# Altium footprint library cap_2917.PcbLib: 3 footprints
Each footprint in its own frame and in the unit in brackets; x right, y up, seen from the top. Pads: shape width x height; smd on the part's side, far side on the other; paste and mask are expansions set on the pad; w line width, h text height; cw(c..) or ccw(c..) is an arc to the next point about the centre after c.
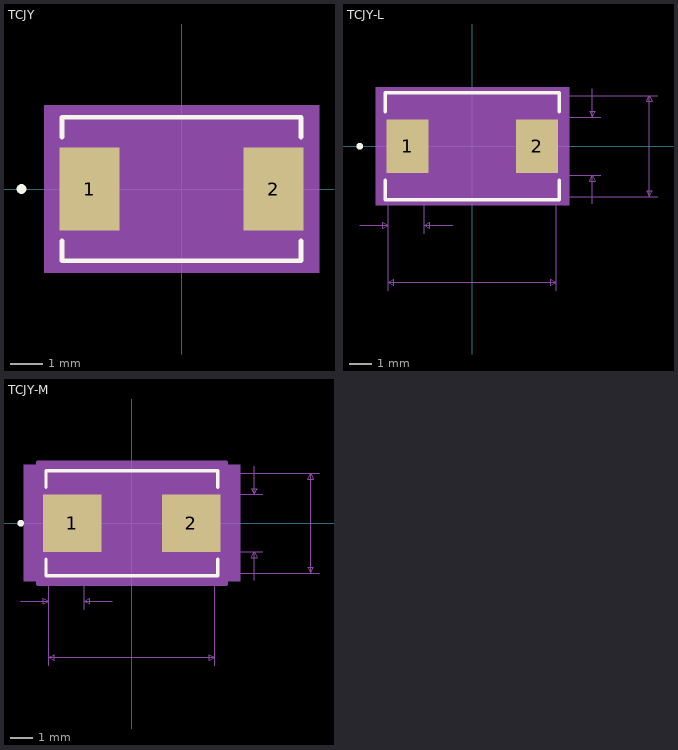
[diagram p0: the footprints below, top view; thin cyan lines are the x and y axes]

## TCJY [mil]
pads (2):
  rect 74x102 smd: 1(-113.5,0) 2(113.5,0)
Top Overlay:
  circle w6: c-197.5,0 r3
  lines w6: -147.5,-64.1 -147.5,-88.5 147.5,-88.5 147.5,-64.1 ; -147.5,64.1 -147.5,88.5 147.5,88.5 147.5,64.1
Mechanical 5:
  region: 169.5,-103.5 -169.5,-103.5 -169.5,103.5 169.5,103.5
Mechanical 13:
  circle w0: c-197.5,0 r3
  lines w1: -147.5,-88.5 147.5,-88.5 147.5,88.5 -147.5,88.5 -147.5,-88.5
Mechanical 15:
  region: 154.5,-92.5 -154.5,-92.5 -154.5,92.5 154.5,92.5
  lines w6: -154.5,-92.5 -154.5,92.5 154.5,92.5 154.5,-92.5 -154.5,-92.5

## TCJY-L [mil]
pads (2):
  rect 74x94 smd paste+0 mask+0: 1(-113.5,0) 2(113.5,0)
Top Overlay:
  circle w6: c-197.5,0 r3
  lines w6: -152.5,-59.95 -152.5,-93.5 152.5,-93.5 152.5,-59.95 ; -152.5,59.95 -152.5,93.5 152.5,93.5 152.5,59.95
Mechanical 5:
  region: 169.5,-103.5 -169.5,-103.5 -169.5,103.5 169.5,103.5
Mechanical 7:
  lines w1: -197.5,-138.5 -147.5,-138.5 ; -147.5,-253.5 -147.5,0 -147.5,-153.5 ; -84.5,-153.5 -84.5,0 ; -34.5,-138.5 -84.5,-138.5 ; 147.5,-253.5 147.5,0 ; 160.5,-88.5 325.5,-88.5 ; 160.5,-51 225.5,-51 ; 160.5,51 225.5,51 ; 160.5,88.5 325.5,88.5 ; 210.5,-101 210.5,-51 ; 210.5,101 210.5,51 ; -147.5,-238.5 -137.5,-243.5 -137.5,-233.5 -147.5,-238.5 ; -147.5,-238.5 147.5,-238.5 ; -147.5,-138.5 -157.5,-143.5 -157.5,-133.5 -147.5,-138.5 ; -84.5,-138.5 -74.5,-143.5 -74.5,-133.5 -84.5,-138.5 ; 147.5,-238.5 137.5,-243.5 137.5,-233.5 147.5,-238.5 ; 210.5,-51 215.5,-61 205.5,-61 210.5,-51 ; 210.5,51 215.5,61 205.5,61 210.5,51 ; 310.5,-88.5 315.5,-78.5 305.5,-78.5 310.5,-88.5 ; 310.5,-88.5 310.5,88.5 ; 310.5,88.5 315.5,78.5 305.5,78.5 310.5,88.5
  text "0.063in/1.6mm" at -197.25,-183.5 h25
  text "0.295in/7.493mm" at -93.75,-283.5 h25
  text "0.177in/4.496mm" at 330.5,-12.5 h25
  text "0.102in/2.591mm" at 230.5,-12.5 h25
  text "Alt 2 Padstyle: OX90Y60D30P" at -337.5,-513.5 h50
  text "Alt 1 Padstyle: OX60Y90D30P" at -337.5,-438.5 h50
  text "Default Padstyle: RX74Y94D0T" at -350,-363.5 h50
Mechanical 13:
  circle w0: c-137.5,0 r3
  lines w1: -147.5,-88.5 -147.5,88.5 147.5,88.5 147.5,-88.5 -147.5,-88.5
Mechanical 15:
  region: -151.5,-51 -154.5,-51 -154.5,51 -151.5,51 -151.5,92.5 151.5,92.5 151.5,51 154.5,51 154.5,-51 151.5,-51 151.5,-92.5 -151.5,-92.5
  lines w6: -154.5,-51 -151.5,-51 -151.5,-92.5 151.5,-92.5 151.5,-51 154.5,-51 154.5,51 151.5,51 151.5,92.5 -151.5,92.5 -151.5,51 -154.5,51 -154.5,-51

## TCJY-M [mil]
pads (2):
  rect 104x102 smd paste+0 mask+0: 1(-105.5,0) 2(105.5,0)
Top Overlay:
  circle w6: c-197.5,0 r3
  lines w6: -152.5,-64.1 -152.5,-93.5 152.5,-93.5 152.5,-64.1 ; -152.5,64.1 -152.5,93.5 152.5,93.5 152.5,64.1
Mechanical 5:
  region: 192.5,-103.5 -192.5,-103.5 -192.5,103.5 192.5,103.5
Mechanical 7:
  lines w1: -197.5,-138.5 -147.5,-138.5 ; -147.5,-253.5 -147.5,0 -147.5,-153.5 ; -84.5,-153.5 -84.5,0 ; -34.5,-138.5 -84.5,-138.5 ; 147.5,-253.5 147.5,0 ; 167.5,-88.5 332.5,-88.5 ; 167.5,-51 232.5,-51 ; 167.5,51 232.5,51 ; 167.5,88.5 332.5,88.5 ; 217.5,-101 217.5,-51 ; 217.5,101 217.5,51 ; -147.5,-238.5 147.5,-238.5 ; -147.5,-238.5 -137.5,-233.5 -137.5,-243.5 -147.5,-238.5 ; -147.5,-138.5 -157.5,-133.5 -157.5,-143.5 -147.5,-138.5 ; -84.5,-138.5 -74.5,-133.5 -74.5,-143.5 -84.5,-138.5 ; 147.5,-238.5 137.5,-233.5 137.5,-243.5 147.5,-238.5 ; 217.5,-51 212.5,-61 222.5,-61 217.5,-51 ; 217.5,51 212.5,61 222.5,61 217.5,51 ; 317.5,-88.5 317.5,88.5 ; 317.5,-88.5 312.5,-78.5 322.5,-78.5 317.5,-88.5 ; 317.5,88.5 312.5,78.5 322.5,78.5 317.5,88.5
  text "Default Padstyle: RX104Y102D0T" at -375,-363.5 h50
  text "Alt 1 Padstyle: OX60Y90D30P" at -337.5,-438.5 h50
  text "Alt 2 Padstyle: OX90Y60D30P" at -337.5,-513.5 h50
  text "0.102in/2.591mm" at 237.5,-12.5 h25
  text "0.177in/4.496mm" at 337.5,-12.5 h25
  text "0.295in/7.493mm" at -93.75,-283.5 h25
  text "0.063in/1.6mm" at -197.25,-183.5 h25
Mechanical 13:
  circle w0: c-137.5,0 r3
  lines w1: -147.5,-88.5 147.5,-88.5 147.5,88.5 -147.5,88.5 -147.5,-88.5
Mechanical 15:
  region: -167.5,-71 -177.5,-71 -177.5,71 -167.5,71 -167.5,108.5 167.5,108.5 167.5,71 177.5,71 177.5,-71 167.5,-71 167.5,-108.5 -167.5,-108.5
  lines w6: -177.5,-71 -177.5,71 -167.5,71 -167.5,108.5 167.5,108.5 167.5,71 177.5,71 177.5,-71 167.5,-71 167.5,-108.5 -167.5,-108.5 -167.5,-71 -177.5,-71
3D body: height 10, standoff 0, extent 0,0 10,10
